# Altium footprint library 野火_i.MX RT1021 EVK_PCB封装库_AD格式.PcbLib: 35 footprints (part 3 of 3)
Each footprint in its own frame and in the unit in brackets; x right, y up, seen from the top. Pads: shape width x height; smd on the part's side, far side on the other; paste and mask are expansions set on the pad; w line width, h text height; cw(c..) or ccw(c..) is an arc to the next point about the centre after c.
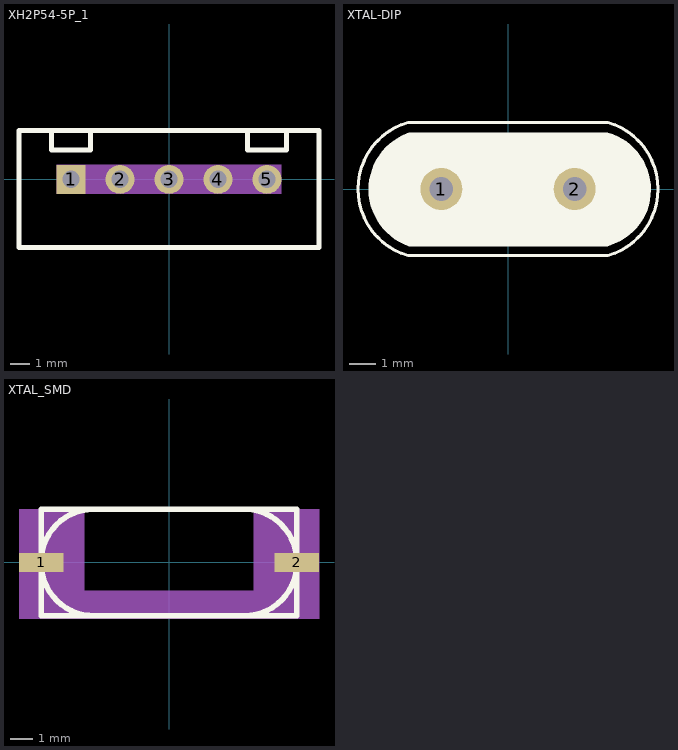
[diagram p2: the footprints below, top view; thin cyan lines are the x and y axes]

## XH2P54-5P_1 [mil] "XH2P54-5P_1"
pads (5):
  rect 59.06x59.06 / inner round 60 / far side rect 59.06x59.06 hole 35.43: 1(-200,0)
  round 59.06 / inner round 60 / far side round 59.06 hole 35.43: 2(-100,0) 3(0,0) 4(100,0) 5(200,0)
Top Overlay:
  lines w10: -306.3,-139.37 -306.3,100 306.3,100 306.3,-139.37 -306.3,-139.37 ; -240,60 -240,100 -160,100 -160,60 -240,60 ; 160,60 160,100 240,100 240,60 160,60
Mechanical 6:
  text "5" at 210,0 h25
  text "2" at -90,0 h25
  text "4" at 110,0 h25
  text "1" at -190,0 h25
  text "3" at 10,0 h25
Mechanical 7:
  region: -229.53,-29.53 229.53,-29.53 229.53,29.53 -229.53,29.53
3D body: height 150, standoff 0, extent -229.53,-29.53 229.53,29.53

## XTAL-DIP [mil] "XTAL-DIP"
pads (2):
  round 62.99 / inner round 60 / far side round 62.99 hole 35.43: 1(-100,0) 2(100,0)
Top Overlay:
  pour cut-out: -148.7,84.49 149.53,84.49 156.85,82.1 163.94,79.08 170.74,75.46 177.2,71.26 183.27,66.51 188.89,61.25 194.04,55.52 198.68,49.36 202.75,42.82 206.24,35.96 209.12,28.81 211.37,21.44 212.96,13.9 213.89,6.26 214.16,-1.44 213.75,-9.14 212.67,-16.76 210.93,-24.27 208.54,-31.59 205.52,-38.68 201.9,-45.48 197.7,-51.94 192.95,-58.01 187.69,-63.63 181.96,-68.78 175.8,-73.42 169.26,-77.49 162.4,-80.98 155.25,-83.86 149.53,-85.67 -148.7,-85.67 -156,-82.75 -163.02,-79.2 -169.7,-75.06 -176,-70.35 -181.86,-65.11 -187.25,-59.37 -192.11,-53.19 -196.41,-46.61 -200.13,-39.68 -203.23,-32.46 -205.69,-24.99 -207.48,-17.33 -208.6,-9.55 -209.04,-1.7 -208.8,6.16 -207.87,13.97 -206.26,21.67 -203.99,29.2 -201.07,36.5 -197.52,43.52 -193.38,50.2 -188.67,56.5 -183.43,62.36 -177.69,67.75 -171.51,72.61 -164.93,76.91 -158,80.63 -150.78,83.73
  lines w4.72: -60,0 -40,0 ; -40,-40 -40,40 ; 40,-40 40,40 ; 40,0 60,0 ; -150,-100 cw(c-120.85,0) -150,100 150,100 cw(c120.85,0) 150,-100 -150,-100 ; -20,-40 20,-40 20,40 -20,40 -20,-40
Mechanical 6:
  text "1" at -100,10 h25
  text "2" at 100,10 h25
Mechanical 7:
  region: -131.5,-31.5 131.5,-31.5 131.5,31.5 -131.5,31.5
3D body: height 150, standoff 0, extent -131.5,-31.5 131.5,31.5

## XTAL_SMD [mm] "XTAL_SMD"
pads (2):
  rect 2x0.85 smd: 1(-5.75,0) 2(5.75,0)
Top Overlay:
  lines w0.254: -3.419,2.4 ccw(c-3.385,0.035) -5.75,0 -5.75,-0.069 ccw(c-3.385,-0.035) -3.35,-2.4 ; 3.35,2.4 cw(c3.385,0.035) 5.75,0.069 5.75,0 cw(c3.385,-0.035) 3.419,-2.4 ; -5.75,-2.4 5.75,-2.4 5.75,2.4 -5.75,2.4 -5.75,-2.4
Mechanical 6:
  text "1" at -5.75,0.254 h0.64
  text "2" at 5.75,0.254 h0.64
Mechanical 7:
  region: -6.75,-2.54 6.75,-2.54 6.75,2.4 3.81,2.4 3.81,-1.27 -3.81,-1.27 -3.81,2.4 -6.75,2.4
3D body: height 3.81, standoff 0, extent -6.75,-2.54 6.75,2.4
